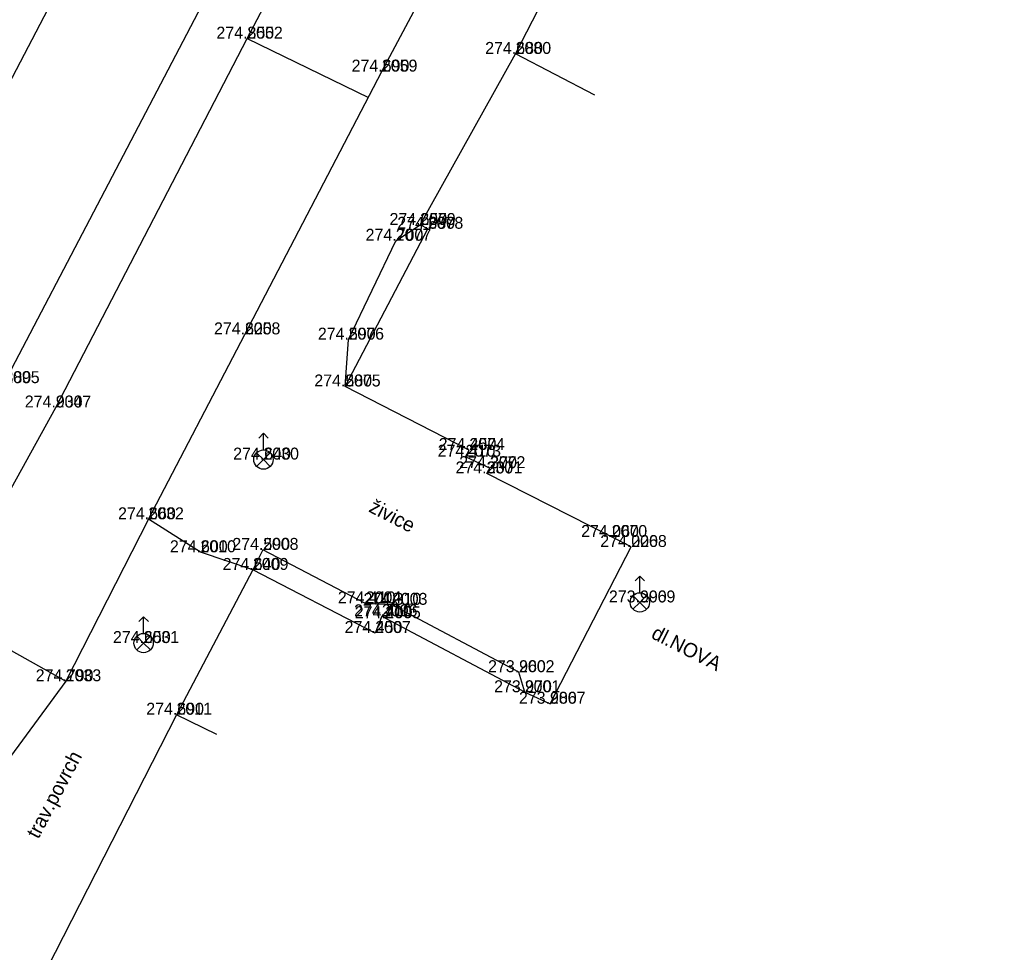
# Model space of a CAD drawing. Extents: x -776701 to -776081, y -974398 to -973771.
# Drawn here: x -776412.71 to -776392.14, y -974187.69 to -974168.17 of the extents above; entities that cross this region are included whole.
import ezdxf

# ---------------------------------------------------------------- set-up
doc = ezdxf.new("R2010")
doc.units = 0
for name, color, linetype in [('1 Body-bod', 7, 'Continuous'), ('10 Silnice-chodniky', 7, 'Continuous'), ('2 Body-cislo', 7, 'Continuous'), ('3 Body-vyska', 7, 'Continuous'), ('40 Popis-povrch', 7, 'Continuous'), ('58 Mobiliar', 7, 'Continuous'), ('7 Ploty', 7, 'Continuous')]:
    doc.layers.add(name, color=color, linetype=linetype)

msp = doc.modelspace()

# ---------------------------------------------------------------- linework, layer by layer
at = {"layer": '1 Body-bod'}
for p, q in [((-776407.95, -974168.57), (-776407.95, -974168.57)), ((-776402.33, -974168.89), (-776402.33, -974168.89)), ((-776405.13, -974169.26), (-776405.13, -974169.26)), ((-776404.33, -974172.47), (-776404.33, -974172.47)), ((-776404.17, -974172.55), (-776404.17, -974172.55)), ((-776404.84, -974172.8), (-776404.84, -974172.8)), ((-776408, -974174.76), (-776408, -974174.76)), ((-776405.83, -974174.87), (-776405.83, -974174.87)), ((-776405.9, -974175.85), (-776405.9, -974175.85)), ((-776411.96, -974176.29), (-776411.96, -974176.29)), ((-776403.3, -974177.18), (-776403.3, -974177.18)), ((-776407.61, -974177.38), (-776407.61, -974177.38)), ((-776403.38, -974177.32), (-776403.38, -974177.32)), ((-776402.93, -974177.67), (-776402.93, -974177.67)), ((-776402.87, -974177.56), (-776402.87, -974177.56)), ((-776410.02, -974178.63), (-776410.02, -974178.63)), ((-776400.32, -974179), (-776400.32, -974179)), ((-776408.93, -974179.32), (-776408.93, -974179.32)), ((-776407.62, -974179.27), (-776407.62, -974179.27)), ((-776399.91, -974179.21), (-776399.91, -974179.21)), ((-776407.83, -974179.69), (-776407.83, -974179.69)), ((-776399.73, -974180.37), (-776399.73, -974180.37)), ((-776405.47, -974180.39), (-776405.47, -974180.39)), ((-776404.92, -974180.42), (-776404.92, -974180.42)), ((-776405.13, -974180.66), (-776405.13, -974180.66)), ((-776405.06, -974180.7), (-776405.06, -974180.7)), ((-776405.27, -974181.01), (-776405.27, -974181.01)), ((-776410.12, -974181.22), (-776410.12, -974181.22)), ((-776411.75, -974182.02), (-776411.75, -974182.02)), ((-776402.26, -974181.83), (-776402.26, -974181.83)), ((-776402.14, -974182.25), (-776402.14, -974182.25)), ((-776401.61, -974182.49), (-776401.61, -974182.49)), ((-776409.43, -974182.72), (-776409.43, -974182.72))]:
    msp.add_line(p, q, dxfattribs=at)
at = {"layer": '10 Silnice-chodniky'}
for points in [[(-776400.67, -974169.754), (-776402.33, -974168.89), (-776398.99, -974162.39), (-776398.9, -974162.43)], [(-776405.9, -974175.85), (-776405.83, -974174.87), (-776404.84, -974172.8), (-776404.33, -974172.47)], [(-776402.14, -974182.25), (-776402.26, -974181.83), (-776404.92, -974180.42), (-776405.47, -974180.39), (-776407.62, -974179.27), (-776407.83, -974179.69), (-776408.93, -974179.32), (-776410.02, -974178.63)], [(-776402.14, -974182.25), (-776401.61, -974182.49), (-776399.91, -974179.21), (-776400.32, -974179)], [(-776404.92, -974180.42), (-776405.06, -974180.7)], [(-776408.585, -974183.134), (-776409.43, -974182.72), (-776412.65, -974189.02), (-776411.65, -974189.55)]]:
    msp.add_lwpolyline(points, dxfattribs=at)
at = {"layer": '58 Mobiliar'}
for p, q in [((-776407.61, -974176.83), (-776407.71, -974176.93)), ((-776407.61, -974177.179), (-776407.61, -974176.83)), ((-776407.61, -974176.83), (-776407.51, -974176.93)), ((-776407.61, -974177.38), (-776407.753, -974177.238)), ((-776407.61, -974177.38), (-776407.468, -974177.238)), ((-776407.61, -974177.38), (-776407.753, -974177.522)), ((-776407.61, -974177.38), (-776407.61, -974177.38)), ((-776407.61, -974177.38), (-776407.468, -974177.522)), ((-776399.73, -974179.82), (-776399.83, -974179.92)), ((-776399.73, -974180.169), (-776399.73, -974179.82)), ((-776399.73, -974179.82), (-776399.63, -974179.92)), ((-776399.73, -974180.37), (-776399.873, -974180.228)), ((-776399.73, -974180.37), (-776399.873, -974180.513)), ((-776399.73, -974180.37), (-776399.588, -974180.228)), ((-776399.73, -974180.37), (-776399.73, -974180.37)), ((-776399.73, -974180.37), (-776399.588, -974180.513)), ((-776410.12, -974180.67), (-776410.22, -974180.77)), ((-776410.12, -974181.019), (-776410.12, -974180.67)), ((-776410.12, -974180.67), (-776410.02, -974180.77)), ((-776410.12, -974181.22), (-776410.263, -974181.078)), ((-776410.12, -974181.22), (-776409.978, -974181.078)), ((-776410.12, -974181.22), (-776410.263, -974181.363)), ((-776410.12, -974181.22), (-776410.12, -974181.22)), ((-776410.12, -974181.22), (-776409.978, -974181.363))]:
    msp.add_line(p, q, dxfattribs=at)
for centre in [(-776407.61, -974177.38), (-776399.73, -974180.37), (-776410.12, -974181.22)]:
    msp.add_circle(centre, 0.202, dxfattribs=at)
at = {"layer": '7 Ploty'}
for p, q in [((-776407.95, -974168.57), (-776405.414, -974169.804)), ((-776414.32, -974180.57), (-776411.75, -974182.02))]:
    msp.add_line(p, q, dxfattribs=at)
for points in [[(-776413.04, -974175.78), (-776408.98, -974168.02), (-776407.17, -974164.6), (-776405.42, -974161.28), (-776404.31, -974159.32), (-776402.54, -974155.81), (-776399.66, -974150.2), (-776396.94, -974145.01), (-776395.76, -974142.69), (-776398.29, -974141.48), (-776399.92, -974144.65), (-776402.16, -974148.88), (-776405.01, -974154.5), (-776406.16, -974156.74), (-776406.74, -974157.8), (-776407.84, -974159.79), (-776411.46, -974166.68), (-776415.53, -974174.46)], [(-776410.02, -974178.63), (-776411.75, -974182.02), (-776414.07, -974185.17), (-776414.88, -974186.15), (-776415.02, -974186.06), (-776417.11, -974188.76), (-776419.58, -974186.86), (-776418.35, -974185.27), (-776418.07, -974185.5), (-776417.25, -974184.38), (-776417.17, -974184.42), (-776416.48, -974183.46), (-776415.65, -974182.42), (-776415.01, -974181.59), (-776414.32, -974180.57), (-776411.96, -974176.29), (-776407.95, -974168.57), (-776405.03, -974163.01), (-776402.53, -974158.19), (-776400.94, -974155.22), (-776397.47, -974148.58), (-776394.68, -974143.21), (-776392.14, -974144.47)], [(-776410.02, -974178.63), (-776408, -974174.76), (-776405.13, -974169.26), (-776402.5, -974164.32), (-776401.35, -974162.09), (-776398.44, -974156.5), (-776396.11, -974152.03), (-776392.14, -974144.47)], [(-776403.3, -974177.18), (-776405.9, -974175.85), (-776404.17, -974172.55), (-776404.33, -974172.47), (-776402.33, -974168.89)], [(-776402.87, -974177.56), (-776403.38, -974177.32), (-776403.3, -974177.18)], [(-776400.32, -974179), (-776402.93, -974177.67), (-776402.87, -974177.56)], [(-776405.27, -974181.01), (-776407.83, -974179.69), (-776409.43, -974182.72)], [(-776402.14, -974182.25), (-776405.06, -974180.7), (-776405.13, -974180.66), (-776405.27, -974181.01)]]:
    msp.add_lwpolyline(points, dxfattribs=at)

# ---------------------------------------------------------------- texts
at = {"layer": '2 Body-cislo'}
for s, p in [('2052', (-776407.95, -974168.57)), ('2080', (-776402.33, -974168.89)), ('2059', (-776405.13, -974169.26)), ('2079', (-776404.33, -974172.47)), ('2078', (-776404.17, -974172.55)), ('2077', (-776404.84, -974172.8)), ('2058', (-776408, -974174.76)), ('2076', (-776405.83, -974174.87)), ('2095', (-776413.04, -974175.78)), ('2075', (-776405.9, -974175.85)), ('2047', (-776411.96, -974176.29)), ('2073', (-776403.38, -974177.32)), ('2074', (-776403.3, -974177.18)), ('2030', (-776407.61, -974177.38)), ('2071', (-776402.93, -974177.67)), ('2072', (-776402.87, -974177.56)), ('2032', (-776410.02, -974178.63)), ('2070', (-776400.32, -974179)), ('2010', (-776408.93, -974179.32)), ('2008', (-776407.62, -974179.27)), ('2068', (-776399.91, -974179.21)), ('2009', (-776407.83, -974179.69)), ('2004', (-776405.47, -974180.39)), ('2003', (-776404.92, -974180.42)), ('2069', (-776399.73, -974180.37)), ('2006', (-776405.13, -974180.66)), ('2005', (-776405.06, -974180.7)), ('2007', (-776405.27, -974181.01)), ('2031', (-776410.12, -974181.22)), ('2002', (-776402.26, -974181.83)), ('2033', (-776411.75, -974182.02)), ('2001', (-776402.14, -974182.25)), ('2067', (-776401.61, -974182.49)), ('2011', (-776409.43, -974182.72))]:
    msp.add_text(s, height=0.25, dxfattribs=at).set_placement(p)
at = {"layer": '3 Body-vyska'}
for s, p in [('274.850', (-776408.595, -974168.57)), ('274.680', (-776402.968, -974168.89)), ('274.690', (-776405.764, -974169.26)), ('274.650', (-776404.971, -974172.47)), ('274.680', (-776404.808, -974172.55)), ('274.700', (-776405.472, -974172.8)), ('274.620', (-776408.645, -974174.76)), ('274.590', (-776406.471, -974174.87)), ('274.880', (-776413.682, -974175.78)), ('274.580', (-776406.545, -974175.85)), ('274.930', (-776412.607, -974176.29)), ('274.410', (-776403.963, -974177.32)), ('274.450', (-776403.941, -974177.18)), ('274.640', (-776408.244, -974177.38)), ('274.330', (-776403.589, -974177.67)), ('274.370', (-776403.511, -974177.56)), ('274.660', (-776410.654, -974178.63)), ('274.060', (-776400.958, -974179)), ('274.600', (-776409.568, -974179.32)), ('274.590', (-776408.261, -974179.27)), ('274.020', (-776400.559, -974179.21)), ('274.640', (-776408.464, -974179.69)), ('274.410', (-776406.053, -974180.39)), ('274.310', (-776405.515, -974180.42)), ('273.990', (-776400.377, -974180.37)), ('274.410', (-776405.713, -974180.66)), ('274.400', (-776405.698, -974180.7)), ('274.450', (-776405.911, -974181.01)), ('274.650', (-776410.761, -974181.22)), ('273.960', (-776402.907, -974181.83)), ('274.790', (-776412.378, -974182.02)), ('273.970', (-776402.781, -974182.25)), ('273.980', (-776402.261, -974182.49)), ('274.690', (-776410.064, -974182.72))]:
    msp.add_text(s, height=0.25, dxfattribs=at).set_placement(p)
at = {"layer": '40 Popis-povrch'}
for s, rotation, p in [('živice', 332.9085, (-776405.426, -974178.462)), ('dl.NOVA', 332.9976, (-776399.512, -974181.107)), ('trav.povrch', 62.1636, (-776412.323, -974185.336))]:
    msp.add_text(s, height=0.3, rotation=rotation, dxfattribs=at).set_placement(p)

doc.saveas('drawing.dxf')
